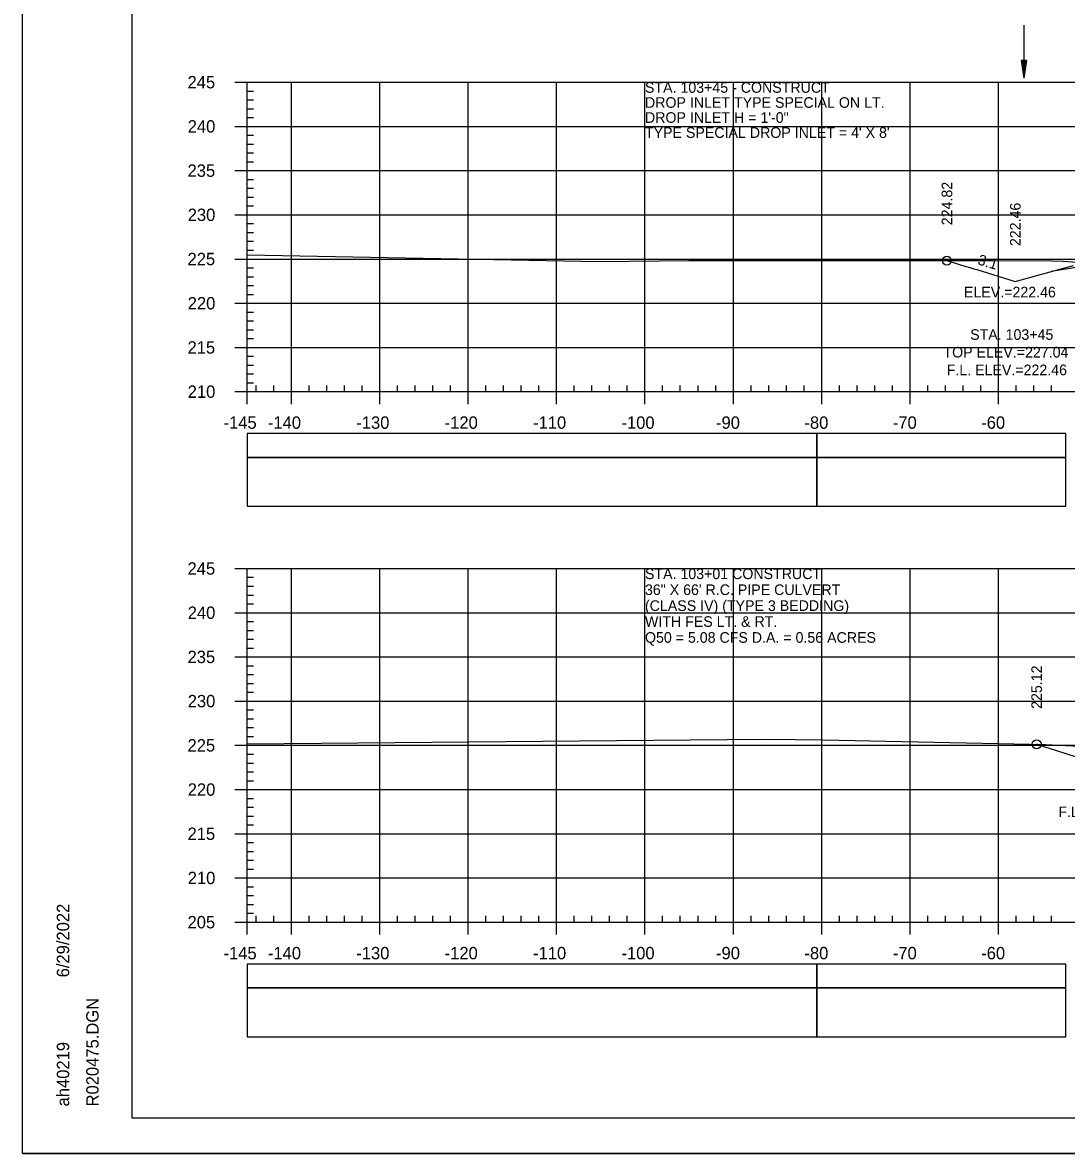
# Model space of a CAD drawing. Extents: x 1386544 to 1388153, y 379785 to 390999.
# Drawn here: x 1386714.8 to 1386832.9, y 380901.3 to 381029.1 of the extents above; entities that cross this region are included whole.
import ezdxf

# ---------------------------------------------------------------- set-up
doc = ezdxf.new("R2010")
doc.units = 0
for name, color, linetype in [('R_Axis', 7, 'Continuous'), ('R_Axis Annot', 7, 'Continuous'), ('R_Border', 7, 'Continuous'), ('R_Exist Surface', 7, 'Continuous'), ('R_Fin Surface', 7, 'Continuous'), ('R_Fin Surface Annot', 7, 'Continuous'), ('R_Grid', 7, 'Continuous'), ('R_No Plot', 7, 'Continuous'), ('R_Striping', 7, 'Continuous'), ('R_Water', 7, 'Continuous'), ('R_Water Annot', 7, 'Continuous')]:
    doc.layers.add(name, color=color, linetype=linetype)

msp = doc.modelspace()

# ---------------------------------------------------------------- linework, layer by layer
at = {"layer": 'R_Axis'}
for p, q in [((1386738.84, 381022.41), (1386740.24, 381022.41)), ((1386740.24, 380987.41), (1386740.24, 381022.41)), ((1386740.24, 381021.41), (1386740.94, 381021.41)), ((1386740.24, 381020.41), (1386740.94, 381020.41)), ((1386740.24, 381019.41), (1386740.94, 381019.41)), ((1386740.24, 381018.41), (1386740.94, 381018.41)), ((1386738.84, 381017.41), (1386740.24, 381017.41)), ((1386740.24, 381016.41), (1386740.94, 381016.41)), ((1386740.24, 381015.41), (1386740.94, 381015.41)), ((1386740.24, 381014.41), (1386740.94, 381014.41)), ((1386740.24, 381013.41), (1386740.94, 381013.41)), ((1386738.84, 381012.41), (1386740.24, 381012.41)), ((1386740.24, 381011.41), (1386740.94, 381011.41)), ((1386740.24, 381010.41), (1386740.94, 381010.41)), ((1386740.24, 381009.41), (1386740.94, 381009.41)), ((1386740.24, 381008.41), (1386740.94, 381008.41)), ((1386738.84, 381007.41), (1386740.24, 381007.41)), ((1386740.24, 381006.41), (1386740.94, 381006.41)), ((1386740.24, 381005.41), (1386740.94, 381005.41)), ((1386740.24, 381004.41), (1386740.94, 381004.41)), ((1386740.24, 381003.41), (1386740.94, 381003.41)), ((1386738.84, 381002.41), (1386740.24, 381002.41)), ((1386740.24, 381001.41), (1386740.94, 381001.41)), ((1386740.24, 381000.41), (1386740.94, 381000.41)), ((1386740.24, 380999.41), (1386740.94, 380999.41)), ((1386740.24, 380998.41), (1386740.94, 380998.41)), ((1386738.84, 380997.41), (1386740.24, 380997.41)), ((1386740.24, 380996.41), (1386740.94, 380996.41)), ((1386740.24, 380995.41), (1386740.94, 380995.41)), ((1386740.24, 380994.41), (1386740.94, 380994.41)), ((1386738.84, 380992.41), (1386740.24, 380992.41)), ((1386740.24, 380993.41), (1386740.94, 380993.41)), ((1386740.24, 380991.41), (1386740.94, 380991.41)), ((1386740.24, 380990.41), (1386740.94, 380990.41)), ((1386740.24, 380989.41), (1386740.94, 380989.41)), ((1386738.84, 380987.41), (1386740.24, 380987.41)), ((1386740.24, 380988.41), (1386740.94, 380988.41)), ((1386740.24, 380987.41), (1386740.24, 380988.11)), ((1386740.24, 380987.41), (1387030.24, 380987.41)), ((1386740.24, 380986.01), (1386740.24, 380987.41)), ((1386741.24, 380987.41), (1386741.24, 380988.11)), ((1386743.24, 380987.41), (1386743.24, 380988.11)), ((1386745.24, 380986.01), (1386745.24, 380987.41)), ((1386747.24, 380987.41), (1386747.24, 380988.11)), ((1386749.24, 380987.41), (1386749.24, 380988.11)), ((1386751.24, 380987.41), (1386751.24, 380988.11)), ((1386753.24, 380987.41), (1386753.24, 380988.11)), ((1386755.24, 380986.01), (1386755.24, 380987.41)), ((1386757.24, 380987.41), (1386757.24, 380988.11)), ((1386759.24, 380987.41), (1386759.24, 380988.11)), ((1386761.24, 380987.41), (1386761.24, 380988.11)), ((1386763.24, 380987.41), (1386763.24, 380988.11)), ((1386765.24, 380986.01), (1386765.24, 380987.41)), ((1386767.24, 380987.41), (1386767.24, 380988.11)), ((1386769.24, 380987.41), (1386769.24, 380988.11)), ((1386771.24, 380987.41), (1386771.24, 380988.11)), ((1386773.24, 380987.41), (1386773.24, 380988.11)), ((1386775.24, 380986.01), (1386775.24, 380987.41)), ((1386777.24, 380987.41), (1386777.24, 380988.11)), ((1386779.24, 380987.41), (1386779.24, 380988.11)), ((1386781.24, 380987.41), (1386781.24, 380988.11)), ((1386783.24, 380987.41), (1386783.24, 380988.11)), ((1386785.24, 380986.01), (1386785.24, 380987.41)), ((1386787.24, 380987.41), (1386787.24, 380988.11)), ((1386789.24, 380987.41), (1386789.24, 380988.11)), ((1386791.24, 380987.41), (1386791.24, 380988.11)), ((1386793.24, 380987.41), (1386793.24, 380988.11)), ((1386795.24, 380986.01), (1386795.24, 380987.41)), ((1386797.24, 380987.41), (1386797.24, 380988.11)), ((1386799.24, 380987.41), (1386799.24, 380988.11)), ((1386801.24, 380987.41), (1386801.24, 380988.11)), ((1386803.24, 380987.41), (1386803.24, 380988.11)), ((1386805.24, 380986.01), (1386805.24, 380987.41)), ((1386807.24, 380987.41), (1386807.24, 380988.11)), ((1386809.24, 380987.41), (1386809.24, 380988.11)), ((1386811.24, 380987.41), (1386811.24, 380988.11)), ((1386813.24, 380987.41), (1386813.24, 380988.11)), ((1386815.24, 380986.01), (1386815.24, 380987.41)), ((1386817.24, 380987.41), (1386817.24, 380988.11)), ((1386819.24, 380987.41), (1386819.24, 380988.11)), ((1386821.24, 380987.41), (1386821.24, 380988.11)), ((1386823.24, 380987.41), (1386823.24, 380988.11)), ((1386825.24, 380986.01), (1386825.24, 380987.41)), ((1386827.24, 380987.41), (1386827.24, 380988.11)), ((1386829.24, 380987.41), (1386829.24, 380988.11)), ((1386831.24, 380987.41), (1386831.24, 380988.11)), ((1386738.84, 380967.41), (1386740.24, 380967.41)), ((1386740.24, 380927.41), (1386740.24, 380967.41)), ((1386740.24, 380966.41), (1386740.94, 380966.41)), ((1386740.24, 380965.41), (1386740.94, 380965.41)), ((1386740.24, 380964.41), (1386740.94, 380964.41)), ((1386740.24, 380963.41), (1386740.94, 380963.41)), ((1386738.84, 380962.41), (1386740.24, 380962.41)), ((1386740.24, 380961.41), (1386740.94, 380961.41)), ((1386740.24, 380960.41), (1386740.94, 380960.41)), ((1386740.24, 380959.41), (1386740.94, 380959.41)), ((1386740.24, 380958.41), (1386740.94, 380958.41)), ((1386738.84, 380957.41), (1386740.24, 380957.41)), ((1386740.24, 380956.41), (1386740.94, 380956.41)), ((1386740.24, 380955.41), (1386740.94, 380955.41)), ((1386740.24, 380954.41), (1386740.94, 380954.41)), ((1386740.24, 380953.41), (1386740.94, 380953.41)), ((1386738.84, 380952.41), (1386740.24, 380952.41)), ((1386740.24, 380951.41), (1386740.94, 380951.41)), ((1386740.24, 380950.41), (1386740.94, 380950.41)), ((1386740.24, 380949.41), (1386740.94, 380949.41)), ((1386740.24, 380948.41), (1386740.94, 380948.41)), ((1386738.84, 380947.41), (1386740.24, 380947.41)), ((1386740.24, 380946.41), (1386740.94, 380946.41)), ((1386740.24, 380945.41), (1386740.94, 380945.41)), ((1386740.24, 380944.41), (1386740.94, 380944.41)), ((1386740.24, 380943.41), (1386740.94, 380943.41)), ((1386738.84, 380942.41), (1386740.24, 380942.41)), ((1386740.24, 380941.41), (1386740.94, 380941.41)), ((1386740.24, 380940.41), (1386740.94, 380940.41)), ((1386740.24, 380939.41), (1386740.94, 380939.41)), ((1386738.84, 380937.41), (1386740.24, 380937.41)), ((1386740.24, 380938.41), (1386740.94, 380938.41)), ((1386740.24, 380936.41), (1386740.94, 380936.41)), ((1386740.24, 380935.41), (1386740.94, 380935.41)), ((1386740.24, 380934.41), (1386740.94, 380934.41)), ((1386738.84, 380932.41), (1386740.24, 380932.41)), ((1386740.24, 380933.41), (1386740.94, 380933.41)), ((1386740.24, 380931.41), (1386740.94, 380931.41)), ((1386740.24, 380930.41), (1386740.94, 380930.41)), ((1386740.24, 380929.41), (1386740.94, 380929.41)), ((1386740.24, 380928.41), (1386740.94, 380928.41)), ((1386738.84, 380927.41), (1386740.24, 380927.41)), ((1386740.24, 380927.41), (1386740.24, 380928.11)), ((1386740.24, 380927.41), (1387030.24, 380927.41)), ((1386740.24, 380926.01), (1386740.24, 380927.41)), ((1386741.24, 380927.41), (1386741.24, 380928.11)), ((1386743.24, 380927.41), (1386743.24, 380928.11)), ((1386745.24, 380926.01), (1386745.24, 380927.41)), ((1386747.24, 380927.41), (1386747.24, 380928.11)), ((1386749.24, 380927.41), (1386749.24, 380928.11)), ((1386751.24, 380927.41), (1386751.24, 380928.11)), ((1386753.24, 380927.41), (1386753.24, 380928.11)), ((1386755.24, 380926.01), (1386755.24, 380927.41)), ((1386757.24, 380927.41), (1386757.24, 380928.11)), ((1386759.24, 380927.41), (1386759.24, 380928.11)), ((1386761.24, 380927.41), (1386761.24, 380928.11)), ((1386763.24, 380927.41), (1386763.24, 380928.11)), ((1386765.24, 380926.01), (1386765.24, 380927.41)), ((1386767.24, 380927.41), (1386767.24, 380928.11)), ((1386769.24, 380927.41), (1386769.24, 380928.11)), ((1386771.24, 380927.41), (1386771.24, 380928.11)), ((1386773.24, 380927.41), (1386773.24, 380928.11)), ((1386775.24, 380926.01), (1386775.24, 380927.41)), ((1386777.24, 380927.41), (1386777.24, 380928.11)), ((1386779.24, 380927.41), (1386779.24, 380928.11)), ((1386781.24, 380927.41), (1386781.24, 380928.11)), ((1386783.24, 380927.41), (1386783.24, 380928.11)), ((1386785.24, 380926.01), (1386785.24, 380927.41)), ((1386787.24, 380927.41), (1386787.24, 380928.11)), ((1386789.24, 380927.41), (1386789.24, 380928.11)), ((1386791.24, 380927.41), (1386791.24, 380928.11)), ((1386793.24, 380927.41), (1386793.24, 380928.11)), ((1386795.24, 380926.01), (1386795.24, 380927.41)), ((1386797.24, 380927.41), (1386797.24, 380928.11)), ((1386799.24, 380927.41), (1386799.24, 380928.11)), ((1386801.24, 380927.41), (1386801.24, 380928.11)), ((1386803.24, 380927.41), (1386803.24, 380928.11)), ((1386805.24, 380926.01), (1386805.24, 380927.41)), ((1386807.24, 380927.41), (1386807.24, 380928.11)), ((1386809.24, 380927.41), (1386809.24, 380928.11)), ((1386811.24, 380927.41), (1386811.24, 380928.11)), ((1386813.24, 380927.41), (1386813.24, 380928.11)), ((1386815.24, 380926.01), (1386815.24, 380927.41)), ((1386817.24, 380927.41), (1386817.24, 380928.11)), ((1386819.24, 380927.41), (1386819.24, 380928.11)), ((1386821.24, 380927.41), (1386821.24, 380928.11)), ((1386823.24, 380927.41), (1386823.24, 380928.11)), ((1386825.24, 380926.01), (1386825.24, 380927.41)), ((1386827.24, 380927.41), (1386827.24, 380928.11)), ((1386829.24, 380927.41), (1386829.24, 380928.11)), ((1386831.24, 380927.41), (1386831.24, 380928.11))]:
    msp.add_line(p, q, dxfattribs=at)
at = {"layer": 'R_Axis Annot'}
for points in [[(1386740.24, 380979.97), (1386804.67, 380979.97), (1386804.67, 380982.67), (1386740.24, 380982.67)], [(1386740.24, 380974.44), (1386804.67, 380974.44), (1386804.67, 380979.97), (1386740.24, 380979.97)], [(1386740.24, 380919.97), (1386804.67, 380919.97), (1386804.67, 380922.67), (1386740.24, 380922.67)], [(1386740.24, 380914.44), (1386804.67, 380914.44), (1386804.67, 380919.97), (1386740.24, 380919.97)]]:
    msp.add_lwpolyline(points, close=True, dxfattribs=at)
at = {"layer": 'R_Border'}
for p, q in [((1386727.24, 380905.24), (1386727.24, 381110.7)), ((1386727.24, 380905.24), (1386727.24, 380905.24)), ((1387043.42, 380905.24), (1386727.24, 380905.24))]:
    msp.add_line(p, q, dxfattribs=at)
at = {"layer": 'R_Exist Surface'}
for points in [[(1386740.24, 381002.87), (1386780.06, 381002.14), (1386790.21, 381002.24), (1386804.65, 381002.24), (1386808.59, 381002.23), (1386812.54, 381002.23), (1386824.57, 381002.23), (1386831.28, 381002.19), (1386832.55, 381002.16), (1386838.29, 381001.74)], [(1386740.24, 380947.57), (1386798.73, 380948.09), (1386802.25, 380948.07), (1386805.36, 380948.03), (1386816.17, 380947.81), (1386830.55, 380947.51), (1386834.36, 380947.33)]]:
    msp.add_lwpolyline(points, dxfattribs=at)
at = {"layer": 'R_Fin Surface'}
for points in [[(1386819.4, 381002.23), (1386821.55, 381001.58), (1386821.76, 381001.51), (1386821.82, 381001.5), (1386821.98, 381001.45), (1386822.45, 381001.31), (1386822.54, 381001.28), (1386822.78, 381001.21), (1386827.14, 380999.87), (1386832.19, 381001.26), (1386833.73, 381001.69)], [(1386829.55, 380947.53), (1386829.6, 380947.53), (1386830.47, 380947.23), (1386831.67, 380946.85), (1386838.81, 380944.56), (1386842.12, 380943.49), (1386848.89, 380945.71), (1386857.88, 380948.66), (1386865.61, 380948.49), (1386865.94, 380948.48), (1386865.96, 380948.48), (1386866.45, 380948.48), (1386866.45, 380947.99), (1386866.45, 380947.98), (1386866.47, 380947.98), (1386867.45, 380948), (1386885.24, 380948.36), (1386902.24, 380948.02), (1386903.24, 380948), (1386903.24, 380948.5), (1386903.74, 380948.5), (1386911.74, 380948.66), (1386931.76, 380941.98), (1386939.17, 380944.45)]]:
    msp.add_lwpolyline(points, dxfattribs=at)
at = {"layer": 'R_Grid'}
for p, q in [((1386740.24, 381022.41), (1387030.24, 381022.41)), ((1386740.24, 380987.41), (1386740.24, 381022.41)), ((1386745.24, 380987.41), (1386745.24, 381022.41)), ((1386755.24, 380987.41), (1386755.24, 381022.41)), ((1386765.24, 380987.41), (1386765.24, 381022.41)), ((1386775.24, 380987.41), (1386775.24, 381022.41)), ((1386785.24, 380987.41), (1386785.24, 381022.41)), ((1386795.24, 380987.41), (1386795.24, 381022.41)), ((1386805.24, 380987.41), (1386805.24, 381022.41)), ((1386815.24, 380987.41), (1386815.24, 381022.41)), ((1386825.24, 380987.41), (1386825.24, 381022.41)), ((1386740.24, 381017.41), (1387030.24, 381017.41)), ((1386740.24, 381012.41), (1387030.24, 381012.41)), ((1386740.24, 381007.41), (1387030.24, 381007.41)), ((1386740.24, 381002.41), (1387030.24, 381002.41)), ((1386740.24, 380997.41), (1387030.24, 380997.41)), ((1386740.24, 380992.41), (1387030.24, 380992.41)), ((1386740.24, 380987.41), (1387030.24, 380987.41)), ((1386740.24, 380967.41), (1387030.24, 380967.41)), ((1386740.24, 380927.41), (1386740.24, 380967.41)), ((1386745.24, 380927.41), (1386745.24, 380967.41)), ((1386755.24, 380927.41), (1386755.24, 380967.41)), ((1386765.24, 380927.41), (1386765.24, 380967.41)), ((1386775.24, 380927.41), (1386775.24, 380967.41)), ((1386785.24, 380927.41), (1386785.24, 380967.41)), ((1386795.24, 380927.41), (1386795.24, 380967.41)), ((1386805.24, 380927.41), (1386805.24, 380967.41)), ((1386815.24, 380927.41), (1386815.24, 380967.41)), ((1386825.24, 380927.41), (1386825.24, 380967.41)), ((1386740.24, 380962.41), (1387030.24, 380962.41)), ((1386740.24, 380957.41), (1387030.24, 380957.41)), ((1386740.24, 380952.41), (1387030.24, 380952.41)), ((1386740.24, 380947.41), (1387030.24, 380947.41)), ((1386740.24, 380942.41), (1387030.24, 380942.41)), ((1386740.24, 380937.41), (1387030.24, 380937.41)), ((1386740.24, 380932.41), (1387030.24, 380932.41)), ((1386740.24, 380927.41), (1387030.24, 380927.41))]:
    msp.add_line(p, q, dxfattribs=at)
at = {"layer": 'R_No Plot'}
msp.add_line((1386714.84, 380901.26), (1387048.17, 380901.26), dxfattribs=at)
for points in [[(1386714.83, 381114.6), (1387048.17, 381114.6), (1387048.17, 380901.26), (1386714.83, 380901.26)], [(1386961.16, 381110.7), (1386980.78, 381110.7), (1386980.78, 381100.82), (1386996.89, 381100.82), (1387020.09, 381100.82), (1387020.09, 381076.49), (1387043.42, 381076.49), (1387043.42, 380905.24), (1386727.24, 380905.24), (1386727.24, 381110.7)]]:
    msp.add_lwpolyline(points, close=True, dxfattribs=at)
for centre in [(1386819.4, 381002.23), (1386829.55, 380947.53)]:
    msp.add_circle(centre, 0.5, dxfattribs=at)
at = {"layer": 'R_Striping'}
for points in [[(1386804.67, 380979.97), (1386832.86, 380979.97), (1386832.86, 380982.67), (1386804.67, 380982.67)], [(1386804.67, 380974.45), (1386832.86, 380974.45), (1386832.86, 380979.97), (1386804.67, 380979.97)], [(1386804.67, 380919.97), (1386832.86, 380919.97), (1386832.86, 380922.67), (1386804.67, 380922.67)], [(1386804.67, 380914.45), (1386832.86, 380914.45), (1386832.86, 380919.97), (1386804.67, 380919.97)]]:
    msp.add_lwpolyline(points, close=True, dxfattribs=at)
at = {"layer": 'R_Water'}
for p, q in [((1386828.11, 381028.85), (1386828.11, 381022.85)), ((1386827.81, 381024.85), (1386828.11, 381022.85)), ((1386828.41, 381024.85), (1386827.81, 381024.85)), ((1386827.81, 381024.85), (1386828.11, 381022.85)), ((1386828.41, 381024.85), (1386827.81, 381024.85)), ((1386827.86, 381024.85), (1386828.11, 381023.19)), ((1386827.86, 381024.85), (1386828.11, 381023.19)), ((1386827.91, 381024.85), (1386828.11, 381023.53)), ((1386827.91, 381024.85), (1386828.11, 381023.53)), ((1386827.96, 381024.85), (1386828.11, 381023.86)), ((1386827.96, 381024.85), (1386828.11, 381023.86)), ((1386828.01, 381024.85), (1386828.11, 381024.2)), ((1386828.01, 381024.85), (1386828.11, 381024.2)), ((1386828.06, 381024.85), (1386828.11, 381024.54)), ((1386828.06, 381024.85), (1386828.11, 381024.54)), ((1386828.41, 381024.85), (1386828.11, 381022.85)), ((1386828.21, 381024.85), (1386828.11, 381024.2)), ((1386828.31, 381024.85), (1386828.11, 381023.53)), ((1386828.36, 381024.85), (1386828.11, 381023.19)), ((1386828.26, 381024.85), (1386828.11, 381023.86)), ((1386828.16, 381024.85), (1386828.11, 381024.54)), ((1386828.41, 381024.85), (1386828.11, 381022.85)), ((1386828.21, 381024.85), (1386828.11, 381024.2)), ((1386828.31, 381024.85), (1386828.11, 381023.53)), ((1386828.36, 381024.85), (1386828.11, 381023.19)), ((1386828.26, 381024.85), (1386828.11, 381023.86)), ((1386828.16, 381024.85), (1386828.11, 381024.54))]:
    msp.add_line(p, q, dxfattribs=at)
msp.add_lwpolyline([(1386837.97, 381002.11), (1386837.97, 381002.11), (1386831.18, 381000.98)], dxfattribs=at)

# ---------------------------------------------------------------- texts
at = {"layer": 'R_Axis Annot'}
for s, p in [('245', (1386733.49, 381021.71)), ('240', (1386733.51, 381016.71)), ('235', (1386733.49, 381011.71)), ('230', (1386733.51, 381006.71)), ('225', (1386733.49, 381001.71)), ('220', (1386733.51, 380996.71)), ('215', (1386733.49, 380991.71)), ('210', (1386733.51, 380986.71)), ('-145', (1386737.56, 380983.21)), ('-140', (1386742.58, 380983.21)), ('-130', (1386752.58, 380983.21)), ('-120', (1386762.58, 380983.21)), ('-110', (1386772.58, 380983.21)), ('-100', (1386782.58, 380983.21)), ('-90', (1386793.28, 380983.21)), ('-80', (1386803.28, 380983.21)), ('-70', (1386813.28, 380983.21)), ('-60', (1386823.28, 380983.21)), ('245', (1386733.49, 380966.71)), ('240', (1386733.51, 380961.71)), ('235', (1386733.49, 380956.71)), ('230', (1386733.51, 380951.71)), ('225', (1386733.49, 380946.71)), ('220', (1386733.51, 380941.71)), ('215', (1386733.49, 380936.71)), ('210', (1386733.51, 380931.71)), ('205', (1386733.49, 380926.71)), ('-145', (1386737.56, 380923.21)), ('-140', (1386742.58, 380923.21)), ('-130', (1386752.58, 380923.21)), ('-120', (1386762.58, 380923.21)), ('-110', (1386772.58, 380923.21)), ('-100', (1386782.58, 380923.21)), ('-90', (1386793.28, 380923.21)), ('-80', (1386803.28, 380923.21)), ('-70', (1386813.28, 380923.21)), ('-60', (1386823.28, 380923.21))]:
    msp.add_text(s, height=1.4, dxfattribs=at).set_placement(p)
at = {"layer": 'R_Border'}
for s, p in [('6/29/2022', (1386720.1, 380921.17)), ('R020475.DGN', (1386723.43, 380906.57)), ('ah40219', (1386720.1, 380906.57))]:
    msp.add_text(s, height=1.4, rotation=90, dxfattribs=at).set_placement(p)
at = {"layer": 'R_Fin Surface Annot'}
for s, rotation, p in [('224.82', 90, (1386820, 381006.23)), ('222.46', 90, (1386827.74, 381003.87)), ('3:1', 343.4242, (1386822.8, 381001.82)), ('225.12', 90, (1386830.15, 380951.53))]:
    msp.add_text(s, height=1.2, rotation=rotation, dxfattribs=at).set_placement(p)
msp.add_text('ELEV.=222.46', height=1.2, dxfattribs=at).set_placement((1386821.33, 380998.07))
at = {"layer": 'R_Water Annot'}
for s, p in [('STA. 103+45 - CONSTRUCT', (1386785.24, 381021.21)), ('DROP INLET TYPE SPECIAL ON LT.', (1386785.24, 381019.51)), ('DROP INLET H = 1\'-0"', (1386785.24, 381017.81)), ("TYPE SPECIAL DROP INLET = 4' X 8'", (1386785.24, 381016.11)), ('STA. 103+45', (1386822.03, 380993.27)), ('TOP ELEV.=227.04', (1386819.01, 380991.27)), ('F.L. ELEV.=222.46', (1386819.38, 380989.27)), ('STA. 103+01 CONSTRUCT', (1386785.24, 380966.21)), ('36" X 66\' R.C. PIPE CULVERT', (1386785.24, 380964.41)), ('(CLASS IV) (TYPE 3 BEDDING)', (1386785.24, 380962.61)), ('WITH FES LT. & RT.', (1386785.24, 380960.81)), ('Q50 = 5.08 CFS D.A. = 0.56 ACRES', (1386785.24, 380959.01)), ('F.L. INLET LT. = 221.00', (1386832.01, 380939.29))]:
    msp.add_text(s, height=1.2, dxfattribs=at).set_placement(p)

doc.saveas('drawing.dxf')
